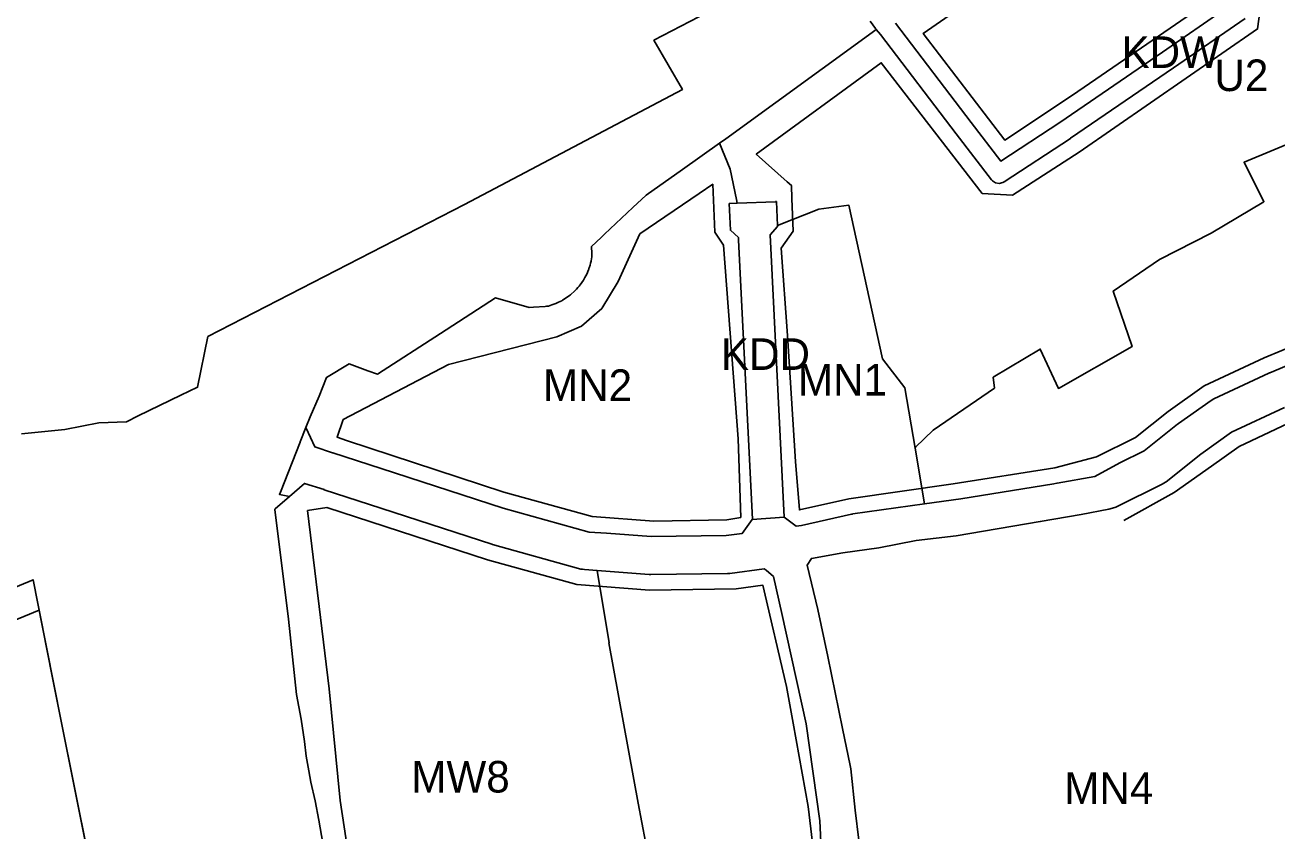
# Model space of a CAD drawing. Extents: x 7425930 to 7427318, y 5544765 to 5546387.
# Drawn here: x 7426439.3 to 7426835.8, y 5545796 to 5546051.3 of the extents above; entities that cross this region are included whole.
import ezdxf

# ---------------------------------------------------------------- set-up
doc = ezdxf.new("R2010")
doc.units = 0
for name, color, linetype in [('linie_rozgraniczajace', 7, 'Continuous'), ('linie_zabudowy_nieprzekraczalne', 7, 'Continuous'), ('linie_zabudowy_obowiazujace', 7, 'Continuous'), ('oznaczenia_przeznaczen', 7, 'Continuous')]:
    doc.layers.add(name, color=color, linetype=linetype)

msp = doc.modelspace()

# ---------------------------------------------------------------- linework, layer by layer
at = {"layer": 'linie_rozgraniczajace'}
for points in [[(7426438.19, 5545921.8), (7426451.87, 5545923.2), (7426462.71, 5545925.28), (7426471.39, 5545925.67), (7426475.16, 5545927.49), (7426488.64, 5545934.03), (7426488.64, 5545934.03), (7426493.94, 5545936.6), (7426497.16, 5545952.63), (7426578.47, 5545994.44), (7426647.5, 5546030.93), (7426638.51, 5546046.52), (7426681.19, 5546068.77)], [(7426856.16, 5546020.62), (7426825.43, 5546007.85), (7426831.7, 5545995.33), (7426815.02, 5545985.39), (7426798.68, 5545977.04), (7426783.99, 5545967.05), (7426789.94, 5545949.48), (7426766.64, 5545936.23), (7426760.84, 5545948.7), (7426745.98, 5545939.75), (7426746.38, 5545936.33), (7426726.93, 5545922.96), (7426726.91, 5545923), (7426721.39, 5545917.63), (7426721.21, 5545917.32), (7426718, 5545936.42), (7426710.92, 5545945.61), (7426700.21, 5545994.3), (7426690.73, 5545992.98), (7426677.62, 5545987.79), (7426677.3, 5545995.39), (7426677.04, 5545995.38), (7426677.02, 5545995.37), (7426664.82, 5545994.88), (7426664.66, 5545996.03), (7426662.68, 5546005.62), (7426659.31, 5546013.86), (7426661.3, 5546015.26), (7426707.6, 5546049), (7426708.92, 5546049.96), (7426710.26, 5546048.28), (7426734.21, 5546016.83), (7426734.22, 5546016.82), (7426734.22, 5546016.82), (7426745.37, 5546002.34), (7426745.71, 5546001.97), (7426746.71, 5546001.36), (7426747.87, 5546001.17), (7426749, 5546001.45), (7426749.39, 5546001.66), (7426770.41, 5546015.42), (7426770.43, 5546015.44), (7426770.46, 5546015.46), (7426803.02, 5546037.8), (7426803.02, 5546037.8), (7426803.02, 5546037.8), (7426825.72, 5546053.45)], [(7426825.72, 5546053.45), (7426803.02, 5546037.8), (7426803.02, 5546037.8), (7426803.02, 5546037.8), (7426770.46, 5546015.46), (7426770.43, 5546015.44), (7426770.41, 5546015.42), (7426749.39, 5546001.66), (7426749, 5546001.45), (7426747.87, 5546001.17), (7426746.71, 5546001.36), (7426745.71, 5546001.97), (7426745.37, 5546002.34), (7426734.22, 5546016.82), (7426734.22, 5546016.82), (7426734.21, 5546016.83), (7426710.26, 5546048.28), (7426708.92, 5546049.96), (7426708.88, 5546050.01), (7426708.72, 5546050.23), (7426707.03, 5546052.55)], [(7426819.79, 5546056.65), (7426799.62, 5546042.74), (7426767.1, 5546020.42), (7426748.43, 5546008.2), (7426738.98, 5546020.47), (7426715.03, 5546051.91)], [(7426715.03, 5546051.91), (7426738.98, 5546020.47), (7426748.43, 5546008.2), (7426767.1, 5546020.42), (7426799.62, 5546042.74), (7426819.79, 5546056.65)], [(7426707.03, 5546052.55), (7426708.72, 5546050.23), (7426708.88, 5546050.01), (7426708.92, 5546049.96), (7426707.6, 5546049), (7426661.3, 5546015.26), (7426659.31, 5546013.86), (7426647.56, 5546005.58), (7426635.99, 5545997.43), (7426631.82, 5545993.51), (7426622.85, 5545985.08), (7426621.78, 5545984.07), (7426618.67, 5545981.14), (7426618.83, 5545978.97), (7426618.86, 5545978.49), (7426618.87, 5545978.38), (7426618.79, 5545977.82), (7426618.73, 5545977.39), (7426618.57, 5545976.49), (7426618.43, 5545975.93), (7426618.28, 5545975.26), (7426618.01, 5545974.45), (7426617.92, 5545974.19), (7426617.85, 5545973.97), (7426617.78, 5545973.81), (7426617.76, 5545973.74), (7426617.22, 5545972.45)], [(7426856.72, 5545950.85), (7426833.54, 5545941.2), (7426833.44, 5545941.13), (7426833.31, 5545941.09), (7426815.89, 5545932.97), (7426815.88, 5545932.96), (7426814.96, 5545932.43), (7426804.66, 5545925.13), (7426804.52, 5545925.01), (7426804.39, 5545924.92), (7426793.77, 5545916.45), (7426786.09, 5545912.66), (7426786.08, 5545912.65), (7426778.13, 5545908.28), (7426766.25, 5545906.22), (7426766.1, 5545906.18), (7426765.17, 5545906.03), (7426735.7, 5545901.29), (7426724.18, 5545899.66), (7426721.21, 5545917.32), (7426721.39, 5545917.63), (7426726.91, 5545923), (7426726.93, 5545922.96), (7426746.38, 5545936.33), (7426745.98, 5545939.75), (7426760.84, 5545948.7), (7426766.64, 5545936.23), (7426789.94, 5545949.48), (7426783.99, 5545967.05), (7426798.68, 5545977.04), (7426815.02, 5545985.39), (7426831.7, 5545995.33), (7426825.43, 5546007.85), (7426856.16, 5546020.62)], [(7426617.22, 5545972.45), (7426616.95, 5545971.91), (7426616.64, 5545971.32), (7426616.17, 5545970.52), (7426615.14, 5545969.02), (7426614.81, 5545968.59), (7426614.44, 5545968.15), (7426613.99, 5545967.71), (7426613.97, 5545967.69), (7426613.86, 5545967.58), (7426613.22, 5545966.95), (7426612.31, 5545966.05), (7426612.11, 5545965.9), (7426611.74, 5545965.61), (7426611.05, 5545965.08), (7426609.55, 5545964.13), (7426609.3, 5545964.01), (7426608.29, 5545963.52), (7426607.47, 5545963.12), (7426606.18, 5545962.67), (7426605.05, 5545962.29), (7426604.42, 5545962.24), (7426604, 5545962.21), (7426600.31, 5545961.92), (7426599, 5545961.81), (7426597.2, 5545962.33), (7426592.29, 5545963.75), (7426588.26, 5545964.92), (7426570.87, 5545953.63), (7426550.95, 5545940.71), (7426547.89, 5545941.84), (7426541.91, 5545944.05), (7426534.82, 5545939.7), (7426532.42, 5545933.76), (7426532.45, 5545933.78), (7426529.64, 5545927.17), (7426528.23, 5545923.83), (7426526.43, 5545919.25), (7426526.42, 5545919.2), (7426520.16, 5545903.39), (7426519.87, 5545902.66), (7426519.9, 5545902.65), (7426523.02, 5545901.94), (7426518.56, 5545898.08), (7426518.37, 5545897.91), (7426518.37, 5545897.9), (7426522.7, 5545863.13), (7426525.27, 5545839.22), (7426526.79, 5545831.49), (7426527.76, 5545824.42), (7426528.32, 5545819.72), (7426529.15, 5545815.13), (7426529.8, 5545811.49), (7426531.17, 5545805.54), (7426532.31, 5545799.5), (7426534.76, 5545785.52)], [(7426519.87, 5545902.66), (7426520.16, 5545903.39), (7426526.42, 5545919.2), (7426526.43, 5545919.25), (7426528.23, 5545923.83), (7426528.33, 5545923.62), (7426531.12, 5545917.67), (7426536.64, 5545915.8), (7426536.73, 5545915.82), (7426552.1, 5545910.86), (7426552.11, 5545910.86), (7426552.11, 5545910.86), (7426590.73, 5545898.33), (7426618, 5545890.73), (7426623.52, 5545890.33), (7426637.57, 5545889.31), (7426661.33, 5545889.59), (7426666.48, 5545890.28), (7426669.64, 5545894.7), (7426679.74, 5545895.43), (7426683.58, 5545892.56), (7426685.2, 5545892.78), (7426701.04, 5545896.37), (7426701.37, 5545896.42), (7426701.53, 5545896.46), (7426724.18, 5545899.66), (7426735.7, 5545901.29), (7426765.17, 5545906.03), (7426766.1, 5545906.18), (7426766.25, 5545906.22), (7426778.13, 5545908.28), (7426786.08, 5545912.65), (7426786.09, 5545912.66), (7426793.77, 5545916.45), (7426804.39, 5545924.92), (7426804.52, 5545925.01), (7426804.66, 5545925.13), (7426814.96, 5545932.43), (7426815.88, 5545932.96), (7426815.89, 5545932.97), (7426833.31, 5545941.09), (7426833.44, 5545941.13), (7426833.54, 5545941.2), (7426856.72, 5545950.85)], [(7426703.39, 5545793.14), (7426702.28, 5545802.62), (7426700.86, 5545815.72), (7426700.7, 5545816.81), (7426698.2, 5545828.51), (7426693.57, 5545851.27), (7426690.36, 5545866.22), (7426687, 5545880.21), (7426688.36, 5545882.35), (7426698.37, 5545884.11), (7426709.68, 5545885.74), (7426721.57, 5545888.05), (7426734.2, 5545889.51), (7426760.85, 5545894.05), (7426773.8, 5545896.31), (7426782.58, 5545897.97), (7426783.78, 5545898.28), (7426784.83, 5545898.65), (7426784.9, 5545898.7), (7426784.97, 5545898.72), (7426799.66, 5545905.98), (7426799.81, 5545906.09), (7426800.75, 5545906.67), (7426811.74, 5545915.44), (7426821.46, 5545922.33), (7426838.26, 5545930.17)], [(7426838.26, 5545930.17), (7426821.46, 5545922.33), (7426811.74, 5545915.44), (7426800.75, 5545906.67)], [(7426534.76, 5545785.52), (7426532.31, 5545799.5), (7426531.17, 5545805.54), (7426529.8, 5545811.49), (7426529.15, 5545815.13), (7426528.32, 5545819.72), (7426527.76, 5545824.42), (7426526.79, 5545831.49), (7426525.27, 5545839.22), (7426522.7, 5545863.13), (7426518.37, 5545897.9), (7426518.37, 5545897.91), (7426518.56, 5545898.08), (7426523.02, 5545901.94), (7426527.84, 5545906.14), (7426534, 5545904.18), (7426534.03, 5545904.08), (7426548.41, 5545899.45), (7426587.14, 5545886.88), (7426587.17, 5545886.87), (7426587.38, 5545886.8), (7426615.36, 5545879.01), (7426615.85, 5545878.95), (7426616.53, 5545878.81), (7426620.56, 5545878.51), (7426624.29, 5545855.65), (7426624.26, 5545855.64), (7426633.53, 5545804.85), (7426638.17, 5545780.35)], [(7426693.16, 5545754.39), (7426691.09, 5545799.24), (7426686.69, 5545830), (7426678.97, 5545864.96), (7426676.39, 5545876.63), (7426674.07, 5545878.66), (7426673.36, 5545879.09), (7426662.56, 5545877.64), (7426662.01, 5545877.6), (7426661.92, 5545877.61), (7426661.83, 5545877.59), (7426637.46, 5545877.3), (7426637.41, 5545877.31), (7426636.95, 5545877.32), (7426620.56, 5545878.51), (7426616.53, 5545878.81), (7426615.85, 5545878.95), (7426615.36, 5545879.01), (7426587.38, 5545886.8), (7426587.17, 5545886.87), (7426587.14, 5545886.88), (7426548.41, 5545899.45), (7426534.03, 5545904.08), (7426534, 5545904.18), (7426527.84, 5545906.14), (7426523.02, 5545901.94), (7426519.9, 5545902.65), (7426519.87, 5545902.66)], [(7426800.75, 5545906.67), (7426799.81, 5545906.09), (7426799.66, 5545905.98), (7426784.97, 5545898.72), (7426784.9, 5545898.7), (7426784.83, 5545898.65), (7426783.78, 5545898.28), (7426782.58, 5545897.97), (7426773.8, 5545896.31), (7426760.85, 5545894.05), (7426734.2, 5545889.51), (7426721.57, 5545888.05), (7426709.68, 5545885.74), (7426698.37, 5545884.11), (7426688.36, 5545882.35), (7426687, 5545880.21), (7426690.36, 5545866.22), (7426693.57, 5545851.27), (7426698.2, 5545828.51), (7426700.7, 5545816.81), (7426700.86, 5545815.72), (7426702.28, 5545802.62), (7426703.39, 5545793.14)], [(7426638.17, 5545780.35), (7426633.53, 5545804.85), (7426624.26, 5545855.64), (7426624.29, 5545855.65), (7426620.56, 5545878.51), (7426636.95, 5545877.32), (7426637.41, 5545877.31), (7426637.46, 5545877.3), (7426661.83, 5545877.59), (7426661.92, 5545877.61), (7426662.01, 5545877.6), (7426662.56, 5545877.64), (7426673.36, 5545879.09), (7426674.07, 5545878.66), (7426676.39, 5545876.63), (7426678.97, 5545864.96), (7426686.69, 5545830), (7426691.09, 5545799.24), (7426693.16, 5545754.39)], [(7426459.42, 5545787.56), (7426447.87, 5545845.05), (7426441.83, 5545875.62), (7426427.49, 5545869.62)], [(7426427.49, 5545869.62), (7426441.83, 5545875.62), (7426447.87, 5545845.05), (7426459.42, 5545787.56)]]:
    msp.add_lwpolyline(points, dxfattribs=at)
for points in [[(7426528.23, 5545923.83), (7426529.64, 5545927.17), (7426532.45, 5545933.78), (7426532.42, 5545933.76), (7426534.82, 5545939.7), (7426541.91, 5545944.05), (7426547.89, 5545941.84), (7426550.95, 5545940.71), (7426570.87, 5545953.63), (7426588.26, 5545964.92), (7426592.29, 5545963.75), (7426597.2, 5545962.33), (7426599, 5545961.81), (7426600.31, 5545961.92), (7426604, 5545962.21), (7426604.42, 5545962.24), (7426605.05, 5545962.29), (7426606.18, 5545962.67), (7426607.47, 5545963.12), (7426608.29, 5545963.52), (7426609.3, 5545964.01), (7426609.55, 5545964.13), (7426611.05, 5545965.08), (7426611.74, 5545965.61), (7426612.11, 5545965.9), (7426612.31, 5545966.05), (7426613.22, 5545966.95), (7426613.86, 5545967.58), (7426613.97, 5545967.69), (7426613.99, 5545967.71), (7426614.44, 5545968.15), (7426614.81, 5545968.59), (7426615.14, 5545969.02), (7426616.17, 5545970.52), (7426616.64, 5545971.32), (7426616.95, 5545971.91), (7426617.22, 5545972.45), (7426617.76, 5545973.74), (7426617.78, 5545973.81), (7426617.85, 5545973.97), (7426617.92, 5545974.19), (7426618.01, 5545974.45), (7426618.28, 5545975.26), (7426618.43, 5545975.93), (7426618.57, 5545976.49), (7426618.73, 5545977.39), (7426618.79, 5545977.82), (7426618.87, 5545978.38), (7426618.86, 5545978.49), (7426618.83, 5545978.97), (7426618.67, 5545981.14), (7426621.78, 5545984.07), (7426622.85, 5545985.08), (7426631.82, 5545993.51), (7426635.99, 5545997.43), (7426647.56, 5546005.58), (7426659.31, 5546013.86), (7426662.68, 5546005.62), (7426664.66, 5545996.03), (7426664.82, 5545994.88), (7426662.37, 5545994.78), (7426662.72, 5545986.32), (7426665.29, 5545984.02), (7426665.33, 5545983.15), (7426669.74, 5545894.85), (7426669.64, 5545894.7), (7426666.48, 5545890.28), (7426661.33, 5545889.59), (7426637.57, 5545889.31), (7426623.52, 5545890.33), (7426618, 5545890.73), (7426590.73, 5545898.33), (7426552.11, 5545910.86), (7426552.11, 5545910.86), (7426552.1, 5545910.86), (7426536.73, 5545915.82), (7426536.64, 5545915.8), (7426531.12, 5545917.67), (7426528.33, 5545923.62)], [(7426662.72, 5545986.32), (7426662.37, 5545994.78), (7426664.82, 5545994.88), (7426677.02, 5545995.37), (7426677.04, 5545995.38), (7426677.3, 5545995.39), (7426677.62, 5545987.79), (7426677.63, 5545987.52), (7426675.27, 5545984.87), (7426675.26, 5545984.87), (7426679.72, 5545895.44), (7426679.74, 5545895.43), (7426669.64, 5545894.7), (7426669.74, 5545894.85), (7426665.33, 5545983.15), (7426665.29, 5545984.02)], [(7426675.26, 5545984.87), (7426675.27, 5545984.87), (7426677.63, 5545987.52), (7426677.62, 5545987.79), (7426690.73, 5545992.98), (7426700.21, 5545994.3), (7426710.92, 5545945.61), (7426718, 5545936.42), (7426721.21, 5545917.32), (7426724.18, 5545899.66), (7426701.53, 5545896.46), (7426701.37, 5545896.42), (7426701.04, 5545896.37), (7426685.2, 5545892.78), (7426683.58, 5545892.56), (7426679.74, 5545895.43), (7426679.72, 5545895.44)]]:
    msp.add_lwpolyline(points, close=True, dxfattribs=at)
at = {"layer": 'linie_zabudowy_nieprzekraczalne'}
for points in [[(7426780.49, 5546102.74), (7426763.18, 5546090.09), (7426750.78, 5546082.43), (7426757.45, 5546072.04), (7426723.77, 5546048.62), (7426749.63, 5546014.9), (7426771.03, 5546029.14), (7426812.77, 5546057.71), (7426780.49, 5546102.61)], [(7426831, 5546060.24), (7426829.69, 5546050.12), (7426773.22, 5546011.09), (7426752.06, 5545997.39), (7426742.51, 5545997.93), (7426710.51, 5546039.39), (7426670.9, 5546010.4), (7426680.66, 5546001.64), (7426682.03, 5546000.51), (7426682.22, 5545996.34), (7426682.64, 5545986.03), (7426678.81, 5545980.65), (7426680.78, 5545953), (7426683.38, 5545913.12), (7426684.57, 5545897.73), (7426700.25, 5545901.21), (7426733.28, 5545906), (7426765.45, 5545911.08), (7426778.68, 5545914.53), (7426791.07, 5545920.66), (7426801.33, 5545928.88), (7426812.78, 5545937.03), (7426831.75, 5545945.87), (7426854.21, 5545955.19)], [(7426665.97, 5545895.28), (7426665.15, 5545920.22), (7426660.58, 5545981.56), (7426657.76, 5545985.68), (7426657.11, 5546000.9), (7426652.8, 5545997.96), (7426633.99, 5545985.15), (7426627.19, 5545970.05), (7426621.97, 5545961.49), (7426615.58, 5545955.94), (7426607.77, 5545952.58), (7426573.37, 5545943.83), (7426540.06, 5545926.33), (7426538.14, 5545920.76), (7426541.09, 5545919.71), (7426590.93, 5545903.4), (7426618.92, 5545895.66), (7426638.44, 5545894.2), (7426661.59, 5545894.61), (7426665.97, 5545895.38)], [(7426817.83, 5545714.78), (7426826.37, 5545723.84), (7426834.78, 5545751.26), (7426836.93, 5545759.67), (7426846.96, 5545785.83), (7426853.37, 5545806.21), (7426861.65, 5545834.56), (7426862.63, 5545841.81), (7426862.59, 5545856.37), (7426862.87, 5545892), (7426860.69, 5545913.21), (7426856.61, 5545925.78), (7426855.16, 5545931.8), (7426839.28, 5545925.06), (7426823.82, 5545917.81), (7426815.07, 5545911.63), (7426803.33, 5545903.3), (7426787.32, 5545894.35)], [(7426569.69, 5545690.72), (7426587.81, 5545695.73), (7426606.67, 5545700.62), (7426616.7, 5545703.11), (7426635.7, 5545706.93), (7426677.92, 5545716.2), (7426689.33, 5545716.53), (7426689.12, 5545752.02), (7426688.79, 5545763.54), (7426689.21, 5545787.87), (7426687.3, 5545803.81), (7426682.63, 5545830.15), (7426680.5, 5545841.74), (7426673, 5545873.88), (7426664.59, 5545872.76), (7426637.08, 5545872.3), (7426614.1, 5545874.15), (7426585.78, 5545881.94), (7426534.93, 5545898.54), (7426528.78, 5545897.54)], [(7426443.73, 5545865.96), (7426432.22, 5545861.25), (7426395.52, 5545845.46), (7426353.35, 5545830.06), (7426347.36, 5545827.81), (7426348.63, 5545820.68), (7426351.91, 5545803.67), (7426353.32, 5545767.25), (7426353.81, 5545745.29), (7426357.55, 5545734.85), (7426361.44, 5545730.11), (7426368.02, 5545724.69), (7426377.36, 5545717.98), (7426413.08, 5545692.56), (7426426.16, 5545681.9), (7426436.87, 5545669.1), (7426455.17, 5545645.48), (7426467.74, 5545629.31)]]:
    msp.add_lwpolyline(points, dxfattribs=at)
at = {"layer": 'linie_zabudowy_obowiazujace'}
for points in [[(7426528.78, 5545897.54), (7426535.58, 5545841.02), (7426539.13, 5545805.68), (7426542.92, 5545780.68), (7426558.59, 5545717.64), (7426565.5, 5545694.09), (7426569.69, 5545690.72)], [(7426467.74, 5545629.44), (7426496.47, 5545649.3), (7426495.86, 5545655.12), (7426490.2, 5545685.14), (7426487.87, 5545696.96), (7426480.68, 5545709.31), (7426455.53, 5545748.54), (7426454.64, 5545750.88), (7426449.16, 5545781.8), (7426448.3, 5545786.31), (7426457.62, 5545787.93), (7426459.3, 5545788.25), (7426450.72, 5545830.85), (7426443.75, 5545865.97)]]:
    msp.add_lwpolyline(points, dxfattribs=at)

# ---------------------------------------------------------------- texts
at = {"layer": 'oznaczenia_przeznaczen'}
for s, p in [('KDW', (7426786.59, 5546037.74)), ('U2', (7426816.01, 5546030.41)), ('KDD', (7426659.69, 5545942.08)), ('MN2', (7426603.35, 5545932.25)), ('MN1', (7426684.1, 5545933.95)), ('MW8', (7426561.62, 5545808.21)), ('MN4', (7426768.46, 5545804.6))]:
    msp.add_text(s, height=10, dxfattribs=at).set_placement(p)

doc.saveas('drawing.dxf')
